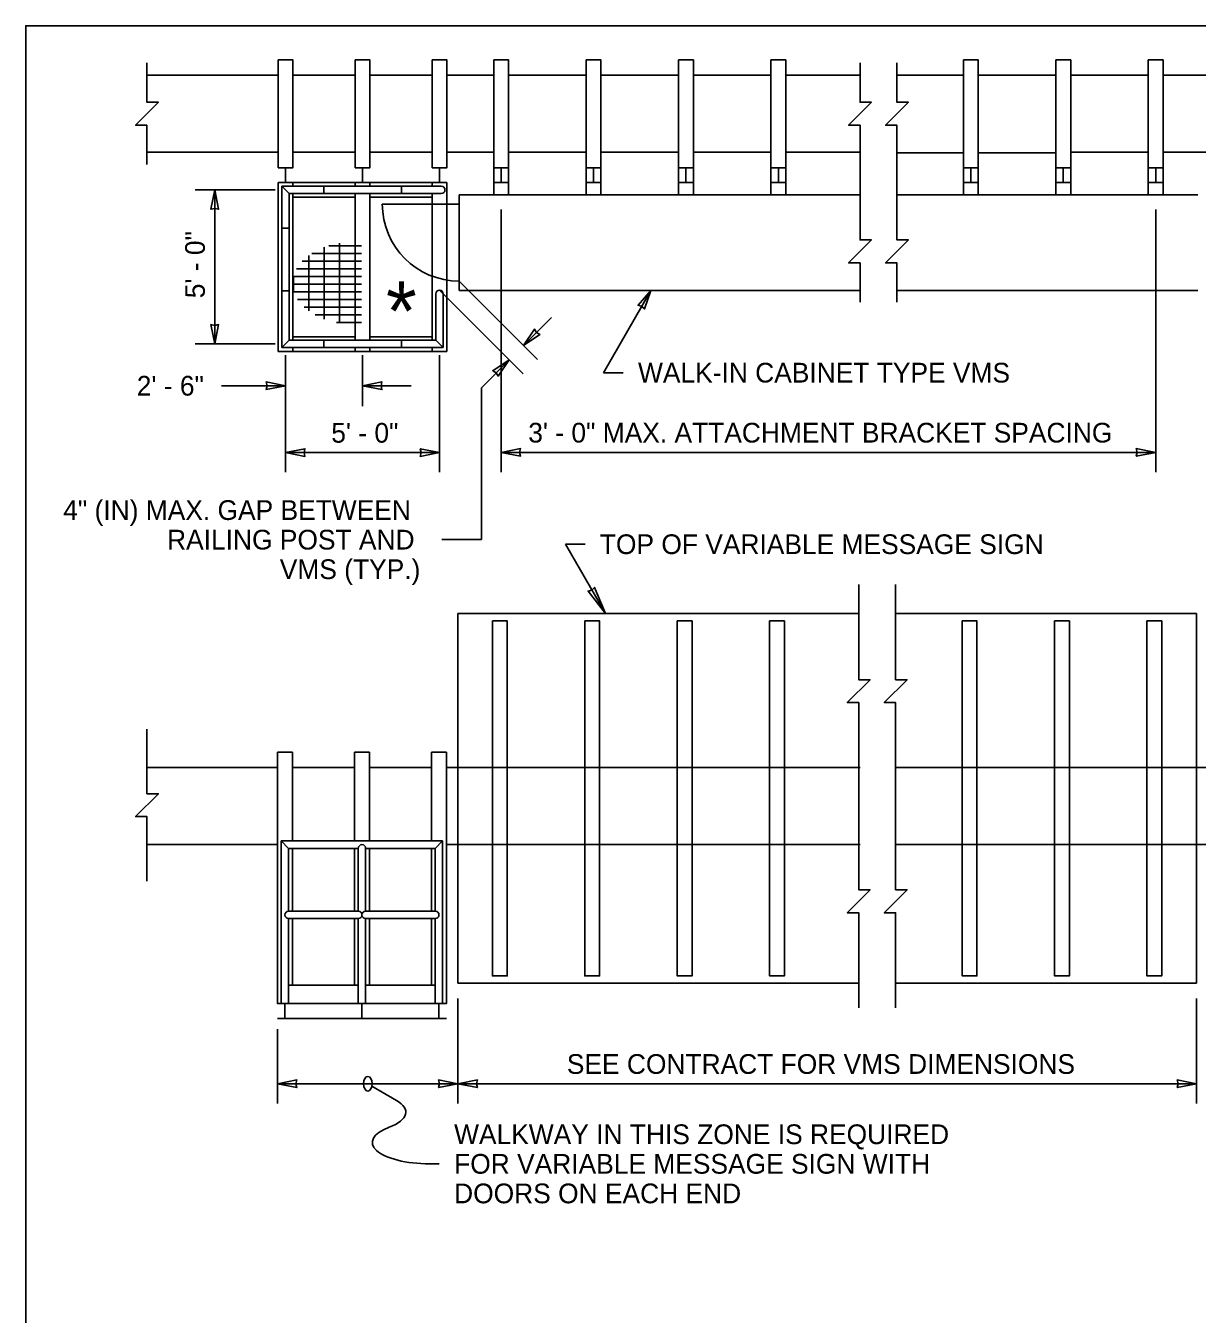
# Model space of a CAD drawing. Extents: x 99862 to 103151, y 100000 to 108076.
# Drawn here: x 99862 to 100813, y 101030 to 102076 of the extents above; entities that cross this region are included whole.
import ezdxf

# ---------------------------------------------------------------- set-up
doc = ezdxf.new("R2010")
doc.units = 0
for name, color, linetype in [('Level 1', 7, 'Continuous'), ('Level 14', 7, 'Continuous'), ('Level 15', 7, 'Continuous'), ('Level 2', 7, 'Continuous'), ('Level 20', 7, 'Continuous'), ('Level 22', 7, 'Continuous'), ('Level 23', 7, 'Continuous'), ('Level 26', 7, 'Continuous'), ('Level 27', 7, 'Continuous')]:
    doc.layers.add(name, color=color, linetype=linetype)

msp = doc.modelspace()

# ---------------------------------------------------------------- linework, layer by layer
at = {"layer": 'Level 1'}
msp.add_lwpolyline([(99862, 99999.5), (103151, 99999.5), (103151, 102075.5), (99862, 102075.5)], close=True, dxfattribs=at)
at = {"layer": 'Level 14'}
msp.add_line((100197.7, 101152), (100189.7, 101152), dxfattribs=at)
for centre, start_param, end_param in [((100124.1, 101194), 5.497747, 6.859209), ((100189.7, 101169.4), 2.356226, 4.712389)]:
    msp.add_ellipse(centre, major_axis=(46.4, 0), ratio=0.375, start_param=start_param, end_param=end_param, dxfattribs=at)
at = {"layer": 'Level 15'}
for p, q in [((99999.4, 101942.3), (100064.5, 101942.3)), ((100015.4, 101817.3), (100015.4, 101942.3)), ((100247.9, 101713.3), (100247.9, 101926.3)), ((100779.2, 101713.3), (100779.2, 101926.3)), ((100213.9, 101868.3), (100277.4, 101804.8)), ((100197.9, 101861), (100265.8, 101793.1)), ((100331, 101794), (100369.5, 101860.8)), ((100288.7, 101838.7), (100266.1, 101816.1)), ((99999.4, 101817.3), (100064.5, 101817.3)), ((100072.9, 101713.3), (100072.9, 101808.1)), ((100135.4, 101808.1), (100135.4, 101766.9)), ((100254.4, 101804.5), (100231.8, 101781.8)), ((100347, 101794), (100331, 101794)), ((100072.9, 101783.4), (100020.8, 101783.4)), ((100174.8, 101783.4), (100135.4, 101783.4)), ((100231.8, 101781.8), (100231.8, 101658.5)), ((100197.9, 101729.2), (100072.9, 101729.2)), ((100247.9, 101729.3), (100779.2, 101729.3)), ((100231.8, 101658.5), (100199.8, 101658.5)), ((100332.5, 101598.5), (100300, 101654.8)), ((100300, 101654.8), (100316, 101654.8)), ((100568.1, 101474), (100568.1, 101426.7)), ((100212.8, 101286.2), (100212.8, 101201)), ((100812.4, 101286.2), (100812.4, 101201)), ((100066.4, 101261.4), (100066.4, 101201)), ((100066.4, 101217), (100212.8, 101217)), ((100142.9, 101215.1), (100163, 101203.5)), ((100212.8, 101217), (100812.4, 101217))]:
    msp.add_line(p, q, dxfattribs=at)
for points in [[(99960.4, 102045.4), (99960.4, 102013.4), (99969.7, 102013.4), (99951.1, 101994.8), (99960.4, 101994.8), (99960.4, 101962.8)], [(100539.2, 102045.4), (100539.2, 102013.4), (100548.5, 102013.4), (100529.9, 101994.8), (100539.2, 101994.8), (100539.2, 101962.8)], [(100569.2, 102045.4), (100569.2, 102013.4), (100578.5, 102013.4), (100559.9, 101994.8), (100569.2, 101994.8), (100569.2, 101962.8)], [(100539.2, 101962.8), (100539.2, 101901.7), (100548.5, 101901.7), (100529.9, 101883.1), (100539.2, 101883.1), (100539.2, 101851.1)], [(100569.2, 101962.8), (100569.2, 101901.7), (100578.5, 101901.7), (100559.9, 101883.1), (100569.2, 101883.1), (100569.2, 101851.1)], [(100538.1, 101622.1), (100538.1, 101544.8), (100547.4, 101544.8), (100528.8, 101526.3), (100538.1, 101526.3), (100538.1, 101374.4), (100547.4, 101374.4), (100528.8, 101355.8), (100538.1, 101355.8), (100538.1, 101278.6)], [(100568.1, 101622.1), (100568.1, 101544.8), (100577.4, 101544.8), (100558.8, 101526.3), (100568.1, 101526.3), (100568.1, 101474)], [(99960.4, 101504.6), (99960.4, 101452.3), (99969.7, 101452.3), (99951.1, 101433.8), (99960.4, 101433.8), (99960.4, 101381.5)], [(100568.1, 101426.7), (100568.1, 101374.4), (100577.4, 101374.4), (100558.8, 101355.8), (100568.1, 101355.8), (100568.1, 101278.6)]]:
    msp.add_lwpolyline(points, dxfattribs=at)
for points in [[(100015.4, 101942.3), (100012.3, 101926.6), (100015.4, 101927.3), (100018.5, 101926.6)], [(100369.5, 101860.8), (100364.3, 101845.7), (100362, 101847.8), (100359, 101848.7)], [(100015.4, 101817.3), (100018.5, 101833), (100015.4, 101832.3), (100012.3, 101833)], [(100266.1, 101816.1), (100279.4, 101825), (100276.7, 101826.7), (100275, 101829.4)], [(100254.4, 101804.5), (100245.5, 101791.2), (100243.8, 101793.9), (100241.1, 101795.5)], [(100072.9, 101783.4), (100057.1, 101786.5), (100057.9, 101783.4), (100057.1, 101780.3)], [(100135.4, 101783.4), (100151.1, 101780.3), (100150.4, 101783.4), (100151.1, 101786.5)], [(100072.9, 101729.2), (100088.6, 101726.1), (100087.9, 101729.2), (100088.6, 101732.3)], [(100197.9, 101729.2), (100182.2, 101732.3), (100182.9, 101729.2), (100182.2, 101726.1)], [(100247.9, 101729.3), (100263.6, 101726.2), (100262.9, 101729.3), (100263.6, 101732.4)], [(100779.2, 101729.3), (100763.4, 101732.4), (100764.2, 101729.3), (100763.4, 101726.2)], [(100332.5, 101598.5), (100323.7, 101619.8), (100321.6, 101617.4), (100318.5, 101616.8)], [(100066.4, 101217), (100082.1, 101213.9), (100081.3, 101217), (100082.1, 101220.1)], [(100212.8, 101217), (100197.1, 101220.1), (100197.8, 101217), (100197.1, 101213.9)], [(100212.8, 101217), (100228.6, 101213.9), (100227.8, 101217), (100228.6, 101220.1)], [(100812.4, 101217), (100796.7, 101220.1), (100797.4, 101217), (100796.7, 101213.9)]]:
    msp.add_lwpolyline(points, close=True, dxfattribs=at)
msp.add_ellipse((100139.6, 101217), major_axis=(0, 6), ratio=0.57735, dxfattribs=at)
at = {"layer": 'Level 2'}
for p, q in [((99960.4, 102035.3), (100066.9, 102035.3)), ((100078.9, 102035.3), (100129.4, 102035.3)), ((100141.4, 102035.3), (100191.9, 102035.3)), ((100203.9, 102035.3), (100241.9, 102035.3)), ((100253.9, 102035.3), (100316.9, 102035.3)), ((100328.9, 102035.3), (100391.9, 102035.3)), ((100403.9, 102035.3), (100466.9, 102035.3)), ((100478.9, 102035.3), (100539.2, 102035.3)), ((100569.2, 102035.3), (100623.2, 102035.3)), ((100635.2, 102035.3), (100698.2, 102035.3)), ((100710.2, 102035.3), (100773.2, 102035.3)), ((100785.2, 102035.3), (100823.2, 102035.3)), ((99960.4, 101972.8), (100066.9, 101972.8)), ((100078.9, 101972.8), (100129.4, 101972.8)), ((100141.4, 101972.8), (100191.9, 101972.8)), ((100203.9, 101972.8), (100241.9, 101972.8)), ((100253.9, 101972.8), (100316.9, 101972.8)), ((100328.9, 101972.8), (100391.9, 101972.8)), ((100403.9, 101972.8), (100466.9, 101972.8)), ((100478.9, 101972.8), (100539.2, 101972.8)), ((100569.2, 101972.5), (100623.2, 101972.5)), ((100635.2, 101972.5), (100698.2, 101972.5)), ((100710.2, 101972.8), (100773.2, 101972.8)), ((100785.2, 101972.8), (100823.2, 101972.8)), ((100066.9, 101960.3), (100078.9, 101960.3)), ((100072.9, 101948.3), (100072.9, 101960.3)), ((100129.4, 101960.3), (100141.4, 101960.3)), ((100135.4, 101948.3), (100135.4, 101960.3)), ((100191.9, 101960.3), (100203.9, 101960.3)), ((100197.9, 101948.3), (100197.9, 101960.3)), ((100241.9, 101960.3), (100253.9, 101960.3)), ((100241.9, 101960.3), (100241.9, 101938.3)), ((100247.9, 101948.3), (100247.9, 101960.3)), ((100253.9, 101960.3), (100253.9, 101938.3)), ((100316.9, 101960.3), (100328.9, 101960.3)), ((100316.9, 101960.3), (100316.9, 101938.3)), ((100322.9, 101948.3), (100322.9, 101960.3)), ((100328.9, 101960.3), (100328.9, 101938.3)), ((100391.9, 101960.3), (100403.9, 101960.3)), ((100391.9, 101960.3), (100391.9, 101938.3)), ((100397.9, 101948.3), (100397.9, 101960.3)), ((100403.9, 101960.3), (100403.9, 101938.3)), ((100466.9, 101960.3), (100478.9, 101960.3)), ((100466.9, 101960.3), (100466.9, 101938.3)), ((100472.9, 101948.3), (100472.9, 101960.3)), ((100478.9, 101960.3), (100478.9, 101938.3)), ((100623.2, 101960.3), (100635.2, 101960.3)), ((100623.2, 101960.3), (100623.2, 101938.3)), ((100629.2, 101948.3), (100629.2, 101960.3)), ((100635.2, 101960.3), (100635.2, 101938.3)), ((100698.2, 101960.3), (100710.2, 101960.3)), ((100698.2, 101960.3), (100698.2, 101938.3)), ((100704.2, 101948.3), (100704.2, 101960.3)), ((100710.2, 101960.3), (100710.2, 101938.3)), ((100773.2, 101960.3), (100785.2, 101960.3)), ((100773.2, 101960.3), (100773.2, 101938.3)), ((100779.2, 101948.3), (100779.2, 101960.3)), ((100785.2, 101960.3), (100785.2, 101938.3)), ((100066.9, 101948.3), (100078.9, 101948.3)), ((100066.9, 101948.3), (100203.9, 101948.3)), ((100066.9, 101811.2), (100066.9, 101948.3)), ((100069.9, 101814.3), (100069.9, 101945.3)), ((100069.9, 101945.3), (100199.3, 101945.3)), ((100069.9, 101945.3), (100075.9, 101939.3)), ((100078.9, 101945.3), (100078.9, 101948.3)), ((100103.9, 101939.3), (100103.9, 101945.3)), ((100129.4, 101948.3), (100141.4, 101948.3)), ((100129.4, 101945.3), (100129.4, 101948.3)), ((100141.4, 101945.3), (100141.4, 101948.3)), ((100166.9, 101939.3), (100166.9, 101945.3)), ((100191.9, 101948.3), (100203.9, 101948.3)), ((100191.9, 101945.3), (100191.9, 101948.3)), ((100203.9, 101811.2), (100203.9, 101948.3)), ((100241.9, 101948.3), (100253.9, 101948.3)), ((100316.9, 101948.3), (100328.9, 101948.3)), ((100391.9, 101948.3), (100403.9, 101948.3)), ((100466.9, 101948.3), (100478.9, 101948.3)), ((100623.2, 101948.3), (100635.2, 101948.3)), ((100698.2, 101948.3), (100710.2, 101948.3)), ((100773.2, 101948.3), (100785.2, 101948.3)), ((100075.9, 101939.3), (100199.3, 101939.3)), ((100075.9, 101820.3), (100075.9, 101939.3)), ((100078.9, 101820.3), (100078.9, 101939.3)), ((100078.9, 101936.3), (100129.4, 101936.3)), ((100129.4, 101820.3), (100129.4, 101939.3)), ((100141.4, 101820.3), (100141.4, 101939.3)), ((100141.4, 101936.3), (100191.9, 101936.3)), ((100151.4, 101930.8), (100213.9, 101930.8)), ((100191.9, 101820.3), (100191.9, 101939.3)), ((100213.9, 101938.3), (100539.2, 101938.3)), ((100213.9, 101860.8), (100213.9, 101938.3)), ((100569.2, 101938.3), (100813.4, 101938.3)), ((100075.9, 101911.3), (100069.9, 101911.3)), ((100075.9, 101860.4), (100069.9, 101860.4)), ((100194.9, 101858), (100194.9, 101820.3)), ((100200.9, 101858), (100200.9, 101814.3)), ((100213.9, 101860.8), (100539.2, 101860.8)), ((100569.2, 101860.8), (100813.4, 101860.8)), ((100069.9, 101814.3), (100075.9, 101820.3)), ((100075.9, 101820.3), (100194.9, 101820.3)), ((100078.9, 101823.2), (100129.4, 101823.2)), ((100103.9, 101814.3), (100103.9, 101820.3)), ((100141.4, 101823.2), (100191.9, 101823.2)), ((100166.9, 101814.3), (100166.9, 101820.3)), ((100194.9, 101820.3), (100200.9, 101814.3)), ((100066.9, 101811.2), (100203.9, 101811.2)), ((100069.9, 101814.3), (100200.9, 101814.3)), ((100078.9, 101811.2), (100078.9, 101814.3)), ((100129.4, 101811.2), (100129.4, 101814.3)), ((100141.4, 101811.2), (100141.4, 101814.3)), ((100191.9, 101811.2), (100191.9, 101814.3)), ((100212.8, 101298.5), (100212.8, 101598.5)), ((100212.8, 101598.5), (100538.1, 101598.5)), ((100568.1, 101598.5), (100812.4, 101598.5)), ((100812.4, 101298.5), (100812.4, 101598.5)), ((99960.4, 101473.5), (100066.4, 101473.5)), ((100078.4, 101473.5), (100128.9, 101473.5)), ((100140.9, 101473.5), (100191.4, 101473.5)), ((100203.4, 101473.5), (100213.9, 101473.5)), ((100213.9, 101473.5), (100539.2, 101473.5)), ((100568.1, 101473.5), (100812.4, 101473.5)), ((100812.4, 101473.5), (100822.1, 101473.5)), ((99960.4, 101411), (100066.4, 101411)), ((100069.4, 101414), (100075.4, 101408)), ((100194.4, 101408), (100200.4, 101414)), ((100203.4, 101411), (100213.9, 101411)), ((100213.9, 101411), (100539.2, 101411)), ((100568.1, 101411), (100812.4, 101411)), ((100812.4, 101411), (100822.1, 101411)), ((100212.8, 101298.5), (100538.1, 101298.5)), ((100568.1, 101298.5), (100812.4, 101298.5))]:
    msp.add_line(p, q, dxfattribs=at)
for points in [[(100066.9, 102047.8), (100078.9, 102047.8), (100078.9, 101960.3), (100066.9, 101960.3)], [(100129.4, 102047.8), (100141.4, 102047.8), (100141.4, 101960.3), (100129.4, 101960.3)], [(100191.9, 102047.8), (100203.9, 102047.8), (100203.9, 101960.3), (100191.9, 101960.3)], [(100241.9, 102047.8), (100253.9, 102047.8), (100253.9, 101960.3), (100241.9, 101960.3)], [(100316.9, 102047.8), (100328.9, 102047.8), (100328.9, 101960.3), (100316.9, 101960.3)], [(100391.9, 102047.8), (100403.9, 102047.8), (100403.9, 101960.3), (100391.9, 101960.3)], [(100466.9, 102047.8), (100478.9, 102047.8), (100478.9, 101960.3), (100466.9, 101960.3)], [(100623.2, 102047.8), (100635.2, 102047.8), (100635.2, 101960.3), (100623.2, 101960.3)], [(100698.2, 102047.8), (100710.2, 102047.8), (100710.2, 101960.3), (100698.2, 101960.3)], [(100773.2, 102047.8), (100785.2, 102047.8), (100785.2, 101960.3), (100773.2, 101960.3)], [(100240.8, 101592.5), (100252.8, 101592.5), (100252.8, 101304.5), (100240.8, 101304.5)], [(100315.8, 101592.5), (100327.8, 101592.5), (100327.8, 101304.5), (100315.8, 101304.5)], [(100390.8, 101592.5), (100402.8, 101592.5), (100402.8, 101304.5), (100390.8, 101304.5)], [(100465.8, 101592.5), (100477.8, 101592.5), (100477.8, 101304.5), (100465.8, 101304.5)], [(100622.1, 101592.5), (100634.1, 101592.5), (100634.1, 101304.5), (100622.1, 101304.5)], [(100697.1, 101592.5), (100709.1, 101592.5), (100709.1, 101304.5), (100697.1, 101304.5)], [(100772.1, 101592.5), (100784.1, 101592.5), (100784.1, 101304.5), (100772.1, 101304.5)]]:
    msp.add_lwpolyline(points, close=True, dxfattribs=at)
for centre, radius, start, end in [((100199.3, 101942.3), 3, 270, 90), ((100213.9, 101930.8), 62.5, 180, 270), ((100197.9, 101858), 3, 0, 180), ((100134.9, 101408), 3, 0, 180), ((100075.4, 101354), 3, 90, 270), ((100131.9, 101354), 3, 270, 90), ((100137.9, 101354), 3, 90, 270), ((100194.4, 101354), 3, 270, 90)]:
    msp.add_arc(centre, radius, start, end, dxfattribs=at)
at = {"layer": 'Level 20'}
msp.add_line((100197.9, 101713.3), (100197.9, 101808.1), dxfattribs=at)
at = {"layer": 'Level 22'}
for points in [[(100078.4, 101282), (100078.4, 101282), (100066.4, 101282), (100066.4, 101486), (100078.4, 101486), (100078.4, 101414)], [(100128.9, 101414), (100128.9, 101486), (100140.9, 101486), (100140.9, 101414)], [(100191.4, 101414), (100191.4, 101486), (100203.4, 101486), (100203.4, 101282), (100191.4, 101282), (100191.4, 101282)], [(100078.4, 101408), (100078.4, 101357)], [(100128.9, 101357), (100128.9, 101408)], [(100140.9, 101408), (100140.9, 101357)], [(100191.4, 101357), (100191.4, 101408)], [(100078.4, 101297), (100078.4, 101351)], [(100128.9, 101297), (100128.9, 101351)], [(100140.9, 101351), (100140.9, 101297)], [(100191.4, 101351), (100191.4, 101297)]]:
    msp.add_lwpolyline(points, dxfattribs=at)
at = {"layer": 'Level 23'}
for p, q in [((100078.4, 101282), (100066.4, 101282)), ((100072.4, 101270), (100072.4, 101282)), ((100140.9, 101282), (100128.9, 101282)), ((100134.9, 101270), (100134.9, 101282)), ((100203.4, 101282), (100191.4, 101282)), ((100197.4, 101270), (100197.4, 101282)), ((100078.4, 101270), (100066.4, 101270)), ((100140.9, 101270), (100128.9, 101270)), ((100203.4, 101270), (100191.4, 101270))]:
    msp.add_line(p, q, dxfattribs=at)
at = {"layer": 'Level 26'}
for p, q in [((100116.8, 101834.1), (100116.8, 101899.2)), ((100129.3, 101833), (100129.3, 101900.3)), ((100091.8, 101844.1), (100091.8, 101889.2)), ((100094.1, 101890.8), (100134.6, 101890.8)), ((100104.3, 101837.5), (100104.3, 101895.8)), ((100107.9, 101897), (100134.6, 101897)), ((100081.7, 101878.3), (100134.6, 101878.3)), ((100086.4, 101884.6), (100134.6, 101884.6)), ((100079.2, 101872.1), (100134.6, 101872.1)), ((100079.3, 101860.8), (100079.3, 101872.5)), ((100078.5, 101865.8), (100134.6, 101865.8)), ((100079.6, 101859.6), (100134.6, 101859.6)), ((100082.7, 101853.4), (100134.6, 101853.4)), ((100088.1, 101847.1), (100134.6, 101847.1)), ((100096.9, 101840.9), (100134.6, 101840.9)), ((100114.1, 101834.6), (100134.6, 101834.6))]:
    msp.add_line(p, q, dxfattribs=at)
at = {"layer": 'Level 27'}
for p, q in [((100069.4, 101414), (100200.4, 101414)), ((100069.4, 101414), (100069.4, 101282)), ((100075.4, 101408), (100131.9, 101408)), ((100075.4, 101357), (100075.4, 101408)), ((100131.9, 101357), (100131.9, 101408)), ((100137.9, 101408), (100194.4, 101408)), ((100137.9, 101357), (100137.9, 101408)), ((100194.4, 101357), (100194.4, 101408)), ((100200.4, 101414), (100200.4, 101282)), ((100075.4, 101357), (100131.9, 101357)), ((100137.9, 101357), (100194.4, 101357)), ((100075.4, 101351), (100131.9, 101351)), ((100075.4, 101351), (100075.4, 101282)), ((100131.9, 101351), (100131.9, 101282)), ((100137.9, 101351), (100194.4, 101351)), ((100137.9, 101351), (100137.9, 101282)), ((100194.4, 101351), (100194.4, 101282)), ((100075.4, 101297), (100131.9, 101297)), ((100137.9, 101297), (100193.8, 101297)), ((100066.4, 101282), (100199.8, 101282)), ((100066.4, 101270), (100203.4, 101270))]:
    msp.add_line(p, q, dxfattribs=at)

# ---------------------------------------------------------------- texts
at = {"layer": 'Level 20'}
msp.add_text('5\' - 0"', height=16, rotation=90, dxfattribs=at).set_placement((100007.4, 101854.4))
for s, height, p in [('*', 48, (100154.4, 101820)), ('WALK-IN CABINET TYPE VMS', 16, (100359, 101786)), ('2\' - 6"', 16, (99952.1, 101775.4)), ('5\' - 0"', 16, (100110, 101737.2)), ('3\' - 0" MAX. ATTACHMENT BRACKET SPACING', 16, (100269.9, 101737.3)), ('4" (IN) MAX. GAP BETWEEN', 16, (99892.4, 101674.5)), ('RAILING POST AND', 16, (99976.7, 101650.5)), ('TOP OF VARIABLE MESSAGE SIGN', 16, (100328, 101646.8)), ('VMS (TYP.)', 16, (100068.2, 101626.5)), ('SEE CONTRACT FOR VMS DIMENSIONS', 16, (100301.2, 101225)), ('WALKWAY IN THIS ZONE IS REQUIRED', 16, (100209.7, 101168)), ('FOR VARIABLE MESSAGE SIGN WITH', 16, (100209.7, 101144)), ('DOORS ON EACH END', 16, (100209.7, 101120))]:
    msp.add_text(s, height=height, dxfattribs=at).set_placement(p)

doc.saveas('drawing.dxf')
